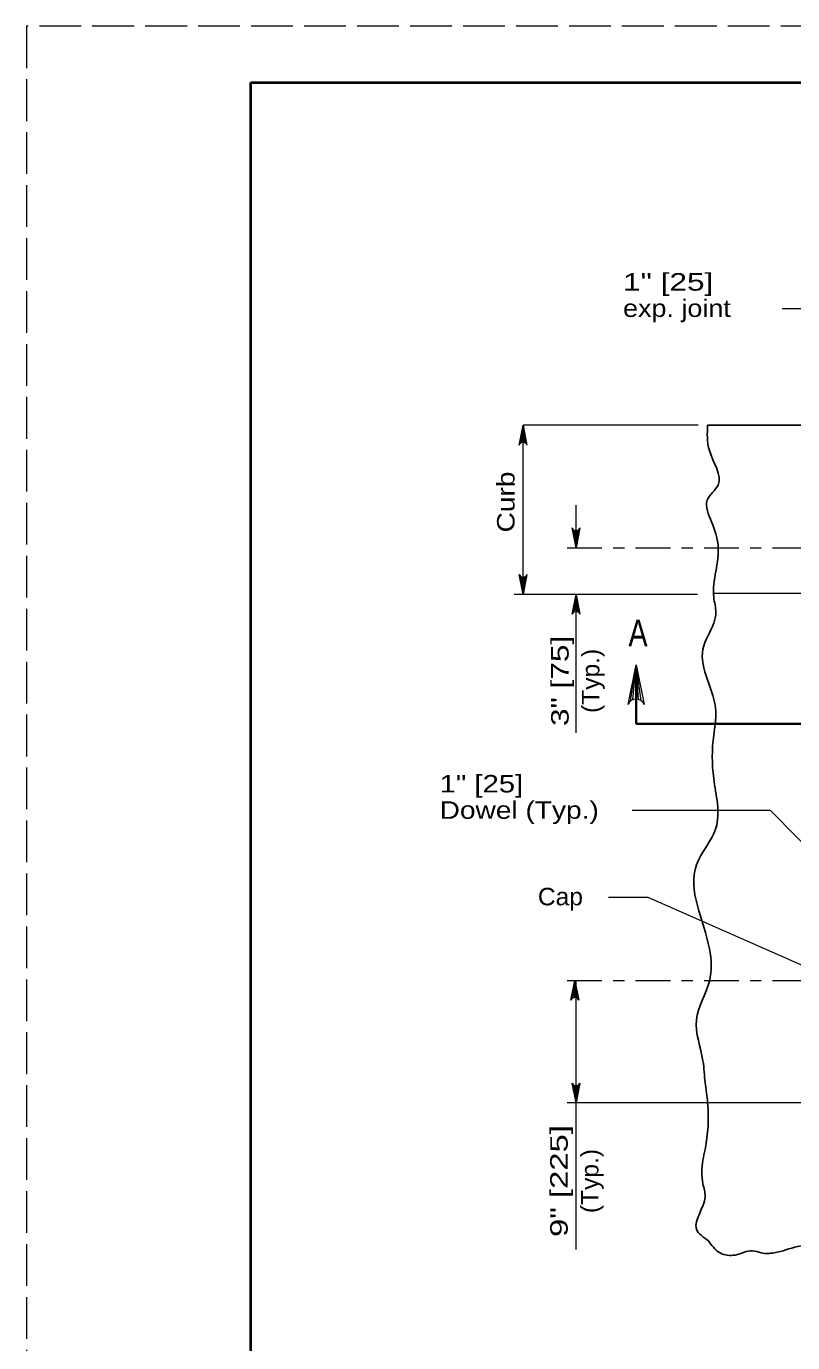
# Model space of a CAD drawing. Extents: x 1083.1 to 1117.1, y 719.4 to 763.4.
# Drawn here: x 1083.13 to 1089.96, y 751.62 to 763.35 of the extents above; entities that cross this region are included whole.
import ezdxf
from ezdxf.enums import TextEntityAlignment as Align

# ---------------------------------------------------------------- set-up
doc = ezdxf.new("R2010")
doc.units = 0
doc.header["$LTSCALE"] = 0.062
doc.linetypes.add('DOT_DASHED', pattern=[7.7, 5, -1.2, 0.3, -1.2])
doc.linetypes.add('LONG_DASHED', pattern=[7.5, 6, -1.5])
doc.layers.add('1', color=7, linetype='Continuous', lineweight=13)

msp = doc.modelspace()

# ---------------------------------------------------------------- linework, layer by layer
at = {"layer": '1', "lineweight": 25}
for p, q in [((1085.12642, 762.85408), (1116.62642, 762.85408)), ((1089.198, 759.79842), (1102.43125, 759.79842))]:
    msp.add_line(p, q, dxfattribs=at)
at = {"layer": '1'}
for p, q in [((1087.52792, 759.63617), (1087.55267, 759.79842)), ((1087.53825, 759.64233), (1087.55267, 759.79842)), ((1087.55267, 759.64517), (1087.55267, 759.79842)), ((1087.564, 759.6435), (1087.55267, 759.79842)), ((1087.57508, 759.63808), (1087.55267, 759.79842)), ((1089.11467, 759.79842), (1087.55267, 759.79842)), ((1087.55267, 758.29042), (1087.55267, 759.79842)), ((1088.02492, 758.70483), (1088.02492, 759.086)), ((1088.00242, 758.86508), (1088.02492, 758.70483)), ((1088.01358, 758.85967), (1088.02492, 758.70483)), ((1088.04967, 758.867), (1088.02492, 758.70483)), ((1088.03925, 758.86083), (1088.02492, 758.70483)), ((1088.02492, 758.858), (1088.02492, 758.70483)), ((1087.53025, 758.45075), (1087.55267, 758.29042)), ((1087.54133, 758.44533), (1087.55267, 758.29042)), ((1087.5775, 758.45267), (1087.55267, 758.29042)), ((1087.56708, 758.4465), (1087.55267, 758.29042)), ((1087.55267, 758.44367), (1087.55267, 758.29042)), ((1089.108, 758.29042), (1087.474, 758.29042)), ((1088.00008, 758.12825), (1088.02492, 758.29042)), ((1088.0105, 758.13442), (1088.02492, 758.29042)), ((1088.02492, 757.05575), (1088.02492, 758.29042)), ((1088.02492, 758.13725), (1088.02492, 758.29042)), ((1088.03625, 758.13558), (1088.02492, 758.29042)), ((1088.04733, 758.13017), (1088.02492, 758.29042)), ((1093.48525, 758.29858), (1089.25483, 758.29858)), ((1088.51042, 757.338), (1088.56, 757.66242)), ((1088.53117, 757.35025), (1088.56, 757.66242)), ((1088.56, 757.35592), (1088.56, 757.66242)), ((1088.58267, 757.35258), (1088.56, 757.66242)), ((1088.60483, 757.34175), (1088.56, 757.66242)), ((1088.6665, 755.58675), (1088.3145, 755.58675)), ((1090.14967, 754.93542), (1088.6665, 755.58675)), ((1087.99058, 754.68658), (1088.01533, 754.84875)), ((1088.00092, 754.69267), (1088.01533, 754.84875)), ((1088.01533, 754.6955), (1088.01533, 754.84875)), ((1088.02667, 754.69383), (1088.01533, 754.84875)), ((1088.03775, 754.68842), (1088.01533, 754.84875)), ((1088.02492, 752.45067), (1088.02492, 754.84875)), ((1088.00242, 753.91617), (1088.02492, 753.75592)), ((1088.01358, 753.91075), (1088.02492, 753.75592)), ((1088.04967, 753.91808), (1088.02492, 753.75592)), ((1088.03925, 753.91192), (1088.02492, 753.75592)), ((1088.02492, 753.90908), (1088.02492, 753.75592)), ((1091.14975, 753.75592), (1087.94617, 753.75592))]:
    msp.add_line(p, q, dxfattribs=at)
at = {"layer": '1', "linetype": 'DOT_DASHED'}
for p, q in [((1087.94617, 758.70483), (1092.74192, 758.70483)), ((1087.94617, 754.84875), (1093.06475, 754.84875))]:
    msp.add_line(p, q, dxfattribs=at)
at = {"layer": '1', "lineweight": 35}
for p, q in [((1088.56, 757.1365), (1088.56, 757.62075)), ((1093.0845, 757.1365), (1088.56, 757.1365))]:
    msp.add_line(p, q, dxfattribs=at)
at = {"layer": '1', "linetype": 'LONG_DASHED'}
msp.add_lwpolyline([(1083.12642, 741.35408), (1117.12642, 741.35408), (1117.12642, 763.35408), (1083.12642, 763.35408)], close=True, dxfattribs=at)
at = {"layer": '1', "lineweight": 25}
msp.add_lwpolyline([(1116.62642, 741.85408), (1085.12642, 741.85408), (1085.12642, 762.85408)], dxfattribs=at)
at = {"layer": '1', "lineweight": 40}
msp.add_lwpolyline([(1085.12642, 762.85408), (1116.62642, 762.85408), (1116.62642, 741.85408), (1085.12642, 741.85408)], close=True, dxfattribs=at)
msp.add_lwpolyline([(1085.12642, 762.85408), (1116.62642, 762.85408), (1116.62642, 741.85408), (1085.12642, 741.85408)], close=True, dxfattribs=at)
at = {"layer": '1'}
for points in [[(1091.38075, 759.81133), (1090.39117, 760.83558), (1089.86325, 760.83558)], [(1087.51725, 759.62133), (1087.55267, 759.79842), (1087.58808, 759.62133)], [(1088.06033, 758.88192), (1088.02492, 758.70483), (1087.9895, 758.88192)], [(1087.58808, 758.4675), (1087.55267, 758.29042), (1087.51725, 758.4675)], [(1087.9895, 758.11342), (1088.02492, 758.29042), (1088.06033, 758.11342)], [(1088.48917, 757.30825), (1088.56, 757.66242), (1088.63083, 757.30825)], [(1091.18933, 754.912), (1089.75767, 756.3625), (1088.52575, 756.3625)], [(1087.97992, 754.67167), (1088.01533, 754.84875), (1088.05075, 754.67167)], [(1088.06033, 753.933), (1088.02492, 753.75592), (1087.9895, 753.933)]]:
    msp.add_lwpolyline(points, dxfattribs=at)
for centre, radius, start, end in [((1087.55272, 759.60701), 0.03822, 22.08782, 157.91395), ((1088.02484, 758.89618), 0.03822, 202.08782, 337.91395), ((1087.55264, 758.48183), 0.03822, 202.08782, 337.91395), ((1088.02492, 758.09908), 0.03822, 22.08782, 157.91395), ((1088.56007, 757.27963), 0.07644, 22.08782, 157.91395), ((1088.01538, 754.65737), 0.03822, 22.08782, 157.91395), ((1088.02484, 753.94727), 0.03822, 202.08782, 337.91395)]:
    msp.add_arc(centre, radius, start, end, dxfattribs=at)
at = {"layer": '1', "lineweight": 25}
for points in [[(1089.198, 759.79842), (1089.21375, 759.57167), (1089.2905, 759.26408), (1089.1945, 759.1295), (1089.23292, 758.93725), (1089.2905, 758.72583), (1089.27125, 758.49508), (1089.252, 758.26433), (1089.27125, 758.12983), (1089.252, 758.03367), (1089.15608, 757.80292), (1089.27125, 757.24542), (1089.252, 757.03392), (1089.252, 756.64942), (1089.27125, 756.20725), (1089.0985, 755.88042), (1089.21375, 755.13058), (1089.21375, 754.84225), (1089.0985, 754.49617), (1089.15608, 754.13083), (1089.17533, 753.93858), (1089.198, 753.75592), (1089.17533, 753.34267), (1089.15608, 753.2465), (1089.15608, 753.035), (1089.17533, 752.91967), (1089.0985, 752.63133), (1089.20592, 752.527)], [(1090.46658, 752.50608), (1090.00083, 752.4775), (1089.78958, 752.41975), (1089.67442, 752.41975), (1089.59758, 752.439), (1089.444, 752.40058), (1089.30967, 752.41975), (1089.198, 752.53517)]]:
    msp.add_spline(points, degree=3, dxfattribs=at)

# ---------------------------------------------------------------- texts
at = {"layer": '1'}
for s, height, width, p in [('1" [25] ', 0.156, 1.35, (1088.44417, 760.99783)), ('exp. joint', 0.156, 1.15, (1088.44417, 760.76317)), ('A', 0.24, 0.8, (1088.49183, 757.82558)), ('1" [25]', 0.156, 1.25, (1086.80942, 756.52408)), ('Dowel (Typ.)', 0.156, 1.2, (1086.80942, 756.28942)), ('Cap', 0.156, 1.05, (1087.685, 755.51817))]:
    msp.add_text(s, height=height, dxfattribs=dict(at, width=width)).set_placement(p)
at = {"layer": '1', "width": 1.2}
msp.add_text('Curb', height=0.156, rotation=90, dxfattribs=at).set_placement((1087.47725, 758.84242))
at = {"layer": '1'}
for s, width, p in [('3" [75]', 1.35, (1087.95917, 757.51887)), ('(Typ.)', 1.05, (1088.23325, 757.51887)), ('9" [225]', 1.4, (1087.95092, 753.05996)), ('(Typ.)', 1.05, (1088.225, 753.06004))]:
    msp.add_text(s, height=0.156, rotation=90, dxfattribs=dict(at, width=width)).set_placement(p, align=Align.CENTER)

doc.saveas('drawing.dxf')
